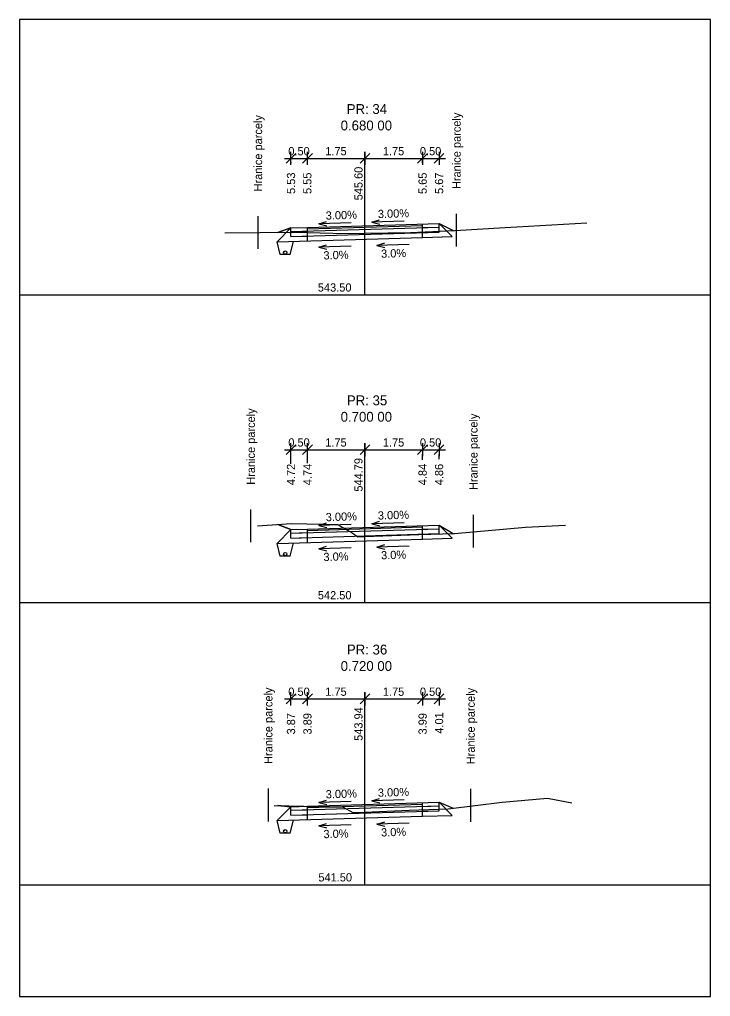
# Model space of a CAD drawing. Extents: x -603737 to -603383, y -1112154 to -1112124.
# Drawn here: x -603429.24 to -603408.24, y -1112153.84 to -1112124.14 of the extents above; entities that cross this region are included whole.
import ezdxf

# ---------------------------------------------------------------- set-up
doc = ezdxf.new("R2010")
doc.units = 0
for name, color, linetype in [('_křivky z hran', 7, 'Continuous'), ('_netisk', 7, 'Continuous'), ('C3D_Podsestava-Popis', 7, 'Continuous'), ('C3D_PP-Popisek', 7, 'Continuous'), ('C3D_PR', 7, 'Continuous'), ('C3D_ZPR', 7, 'Continuous'), ('Default', 7, 'Continuous'), ('konstrukce', 7, 'Continuous')]:
    doc.layers.add(name, color=color, linetype=linetype)

# ---------------------------------------------------------------- blocks, each defined once
blk = doc.blocks.new('_Oblique')
at = {"layer": 'Default'}
blk.add_line((-0.5, -0.5), (0.5, 0.5), dxfattribs=at)
blk = doc.blocks.new('AeccTickLine')
at = {"layer": 'Default'}
blk.add_line((0, 1), (0, -1), dxfattribs=at)

msp = doc.modelspace()

# ---------------------------------------------------------------- linework, layer by layer
at = {"layer": '_netisk'}
msp.add_lwpolyline([(-603429.236, -1112153.84), (-603408.236, -1112153.84), (-603408.236, -1112124.14), (-603429.236, -1112124.14)], close=True, dxfattribs=at)
at = {"layer": 'C3D_Podsestava-Popis'}
for p, q in [((-603421.186, -1112128.361), (-603418.736, -1112128.361)), ((-603418.736, -1112128.361), (-603416.286, -1112128.361)), ((-603416.986, -1112128.511), (-603416.986, -1112128.357)), ((-603416.486, -1112128.342), (-603416.486, -1112128.511)), ((-603420.986, -1112128.477), (-603420.986, -1112128.511)), ((-603420.486, -1112128.511), (-603420.486, -1112128.462)), ((-603418.736, -1112128.511), (-603418.736, -1112128.409)), ((-603421.186, -1112137.217), (-603418.736, -1112137.217)), ((-603418.736, -1112137.217), (-603416.286, -1112137.217)), ((-603420.986, -1112137.645), (-603420.986, -1112137.367)), ((-603420.486, -1112137.63), (-603420.486, -1112137.367)), ((-603418.736, -1112137.577), (-603418.736, -1112137.367)), ((-603416.986, -1112137.525), (-603416.986, -1112137.367)), ((-603416.486, -1112137.51), (-603416.486, -1112137.367)), ((-603421.186, -1112144.794), (-603418.736, -1112144.794)), ((-603418.736, -1112144.794), (-603416.286, -1112144.794)), ((-603418.736, -1112146.003), (-603418.736, -1112144.944))]:
    msp.add_line(p, q, dxfattribs=at)
at = {"layer": 'C3D_PP-Popisek'}
for p, q in [((-603420.139, -1112130.351), (-603419.902, -1112130.276)), ((-603419.155, -1112130.322), (-603420.139, -1112130.351)), ((-603420.139, -1112130.351), (-603419.898, -1112130.412)), ((-603418.528, -1112130.303), (-603418.291, -1112130.227)), ((-603417.544, -1112130.273), (-603418.528, -1112130.303)), ((-603418.528, -1112130.303), (-603418.287, -1112130.364)), ((-603420.139, -1112131.061), (-603419.902, -1112130.986)), ((-603419.155, -1112131.032), (-603420.139, -1112131.061)), ((-603418.374, -1112131.008), (-603418.138, -1112130.933)), ((-603417.391, -1112130.979), (-603418.374, -1112131.008)), ((-603418.374, -1112131.008), (-603418.134, -1112131.069)), ((-603420.139, -1112131.061), (-603419.898, -1112131.122)), ((-603420.139, -1112139.519), (-603419.902, -1112139.444)), ((-603419.155, -1112139.49), (-603420.139, -1112139.519)), ((-603420.139, -1112139.519), (-603419.898, -1112139.58)), ((-603418.528, -1112139.471), (-603418.291, -1112139.395)), ((-603417.544, -1112139.441), (-603418.528, -1112139.471)), ((-603418.528, -1112139.471), (-603418.287, -1112139.532)), ((-603420.139, -1112140.229), (-603419.902, -1112140.154)), ((-603419.155, -1112140.2), (-603420.139, -1112140.229)), ((-603420.139, -1112140.229), (-603419.898, -1112140.29)), ((-603418.374, -1112140.176), (-603418.138, -1112140.101)), ((-603417.391, -1112140.147), (-603418.374, -1112140.176)), ((-603418.374, -1112140.176), (-603418.134, -1112140.237)), ((-603420.139, -1112147.945), (-603419.902, -1112147.87)), ((-603419.155, -1112147.916), (-603420.139, -1112147.945)), ((-603420.139, -1112147.945), (-603419.898, -1112148.006)), ((-603418.528, -1112147.897), (-603418.291, -1112147.821)), ((-603417.544, -1112147.867), (-603418.528, -1112147.897)), ((-603418.528, -1112147.897), (-603418.287, -1112147.958)), ((-603418.374, -1112148.603), (-603418.138, -1112148.527)), ((-603417.391, -1112148.573), (-603418.374, -1112148.603)), ((-603420.139, -1112148.656), (-603419.902, -1112148.58)), ((-603419.155, -1112148.626), (-603420.139, -1112148.656)), ((-603420.139, -1112148.656), (-603419.898, -1112148.717)), ((-603418.374, -1112148.603), (-603418.134, -1112148.664))]:
    msp.add_line(p, q, dxfattribs=at)
at = {"layer": 'C3D_PR'}
for points in [[(-603422.997, -1112130.625), (-603420.874, -1112130.607), (-603419.314, -1112130.648), (-603418.736, -1112130.638), (-603417.356, -1112130.613), (-603416.001, -1112130.553), (-603414.48, -1112130.462), (-603411.991, -1112130.32)], [(-603422.003, -1112139.528), (-603420.968, -1112139.46), (-603419.571, -1112139.493), (-603419.129, -1112139.748), (-603418.951, -1112139.862), (-603418.736, -1112139.855), (-603417.104, -1112139.8), (-603416.015, -1112139.761), (-603413.853, -1112139.573), (-603412.644, -1112139.511)], [(-603421.497, -1112148.031), (-603420.592, -1112148.052), (-603419.396, -1112148.085), (-603419.106, -1112148.252), (-603418.736, -1112148.235), (-603417.397, -1112148.174), (-603416.213, -1112148.134), (-603414.566, -1112147.93), (-603413.19, -1112147.813), (-603412.453, -1112147.95)]]:
    msp.add_lwpolyline(points, dxfattribs=at)
at = {"layer": 'C3D_ZPR'}
for p, q in [((-603418.736, -1112132.511), (-603418.736, -1112128.511)), ((-603421.987, -1112131.116), (-603421.987, -1112130.116)), ((-603415.952, -1112131.043), (-603415.952, -1112130.043)), ((-603420.986, -1112130.587), (-603416.486, -1112130.452)), ((-603420.486, -1112130.462), (-603416.486, -1112130.342)), ((-603420.486, -1112130.502), (-603416.986, -1112130.397)), ((-603416.986, -1112130.397), (-603416.986, -1112130.357)), ((-603416.986, -1112130.767), (-603416.986, -1112130.357)), ((-603416.986, -1112130.467), (-603416.486, -1112130.452)), ((-603416.486, -1112130.602), (-603416.486, -1112130.342)), ((-603416.486, -1112130.602), (-603416.486, -1112130.342)), ((-603416.486, -1112130.342), (-603416.088, -1112130.74)), ((-603416.486, -1112130.342), (-603416.061, -1112130.555)), ((-603416.486, -1112130.342), (-603416.061, -1112130.555)), ((-603421.409, -1112130.899), (-603420.986, -1112130.477)), ((-603420.986, -1112130.477), (-603421.381, -1112130.611)), ((-603421.381, -1112130.611), (-603420.986, -1112130.477)), ((-603420.986, -1112130.477), (-603420.486, -1112130.462)), ((-603420.986, -1112130.737), (-603420.986, -1112130.477)), ((-603420.986, -1112130.737), (-603420.986, -1112130.477)), ((-603420.986, -1112130.587), (-603420.486, -1112130.572)), ((-603420.986, -1112130.737), (-603416.486, -1112130.602)), ((-603420.986, -1112130.737), (-603420.486, -1112130.722)), ((-603420.486, -1112130.872), (-603420.486, -1112130.462)), ((-603420.486, -1112130.572), (-603420.486, -1112130.502)), ((-603420.486, -1112130.872), (-603420.486, -1112130.722)), ((-603416.986, -1112130.617), (-603416.986, -1112130.467)), ((-603416.986, -1112130.617), (-603416.486, -1112130.602)), ((-603416.986, -1112130.767), (-603416.088, -1112130.74)), ((-603421.409, -1112130.899), (-603416.986, -1112130.767)), ((-603429.236, -1112132.511), (-603408.236, -1112132.511)), ((-603418.736, -1112141.867), (-603418.736, -1112137.367)), ((-603422.205, -1112140.033), (-603422.205, -1112139.033)), ((-603415.44, -1112140.193), (-603415.44, -1112139.193)), ((-603421.409, -1112140.067), (-603420.986, -1112139.645)), ((-603420.986, -1112139.645), (-603421.381, -1112139.487)), ((-603421.381, -1112139.487), (-603420.986, -1112139.645)), ((-603420.986, -1112139.755), (-603416.486, -1112139.62)), ((-603420.986, -1112139.645), (-603420.486, -1112139.63)), ((-603420.986, -1112139.905), (-603420.986, -1112139.645)), ((-603420.986, -1112139.905), (-603420.986, -1112139.645)), ((-603420.486, -1112139.63), (-603416.486, -1112139.51)), ((-603420.486, -1112139.67), (-603416.986, -1112139.565)), ((-603420.486, -1112140.04), (-603420.486, -1112139.63)), ((-603416.986, -1112139.565), (-603416.986, -1112139.525)), ((-603416.986, -1112139.935), (-603416.986, -1112139.525)), ((-603416.986, -1112139.635), (-603416.486, -1112139.62)), ((-603416.986, -1112139.785), (-603416.986, -1112139.635)), ((-603416.486, -1112139.77), (-603416.486, -1112139.51)), ((-603416.486, -1112139.77), (-603416.486, -1112139.51)), ((-603416.486, -1112139.51), (-603416.088, -1112139.908)), ((-603416.486, -1112139.51), (-603416.061, -1112139.762)), ((-603416.486, -1112139.51), (-603416.061, -1112139.762)), ((-603421.409, -1112140.067), (-603416.986, -1112139.935)), ((-603420.986, -1112139.755), (-603420.486, -1112139.74)), ((-603420.986, -1112139.905), (-603416.486, -1112139.77)), ((-603420.986, -1112139.905), (-603420.486, -1112139.89)), ((-603420.486, -1112139.74), (-603420.486, -1112139.67)), ((-603420.486, -1112140.04), (-603420.486, -1112139.89)), ((-603416.986, -1112139.785), (-603416.486, -1112139.77)), ((-603416.986, -1112139.935), (-603416.088, -1112139.908)), ((-603429.236, -1112141.867), (-603408.236, -1112141.867)), ((-603418.736, -1112150.444), (-603418.736, -1112144.944)), ((-603421.674, -1112148.521), (-603421.674, -1112147.521)), ((-603415.524, -1112148.532), (-603415.524, -1112147.532)), ((-603420.486, -1112148.056), (-603416.486, -1112147.936)), ((-603416.986, -1112147.991), (-603416.986, -1112147.951)), ((-603416.986, -1112148.361), (-603416.986, -1112147.951)), ((-603416.486, -1112148.196), (-603416.486, -1112147.936)), ((-603416.486, -1112148.196), (-603416.486, -1112147.936)), ((-603416.486, -1112147.936), (-603416.088, -1112148.334)), ((-603416.486, -1112147.936), (-603416.061, -1112148.115)), ((-603416.486, -1112147.936), (-603416.061, -1112148.115)), ((-603421.409, -1112148.494), (-603420.986, -1112148.071)), ((-603420.986, -1112148.071), (-603421.381, -1112148.034)), ((-603421.381, -1112148.034), (-603420.986, -1112148.071)), ((-603420.986, -1112148.181), (-603416.486, -1112148.046)), ((-603420.986, -1112148.071), (-603420.486, -1112148.056)), ((-603420.986, -1112148.331), (-603420.986, -1112148.071)), ((-603420.986, -1112148.331), (-603420.986, -1112148.071)), ((-603420.986, -1112148.181), (-603420.486, -1112148.166)), ((-603420.986, -1112148.331), (-603416.486, -1112148.196)), ((-603420.486, -1112148.096), (-603416.986, -1112147.991)), ((-603420.486, -1112148.466), (-603420.486, -1112148.056)), ((-603420.486, -1112148.166), (-603420.486, -1112148.096)), ((-603416.986, -1112148.061), (-603416.486, -1112148.046)), ((-603416.986, -1112148.211), (-603416.986, -1112148.061)), ((-603416.986, -1112148.211), (-603416.486, -1112148.196)), ((-603421.409, -1112148.494), (-603416.986, -1112148.361)), ((-603420.986, -1112148.331), (-603420.486, -1112148.316)), ((-603420.486, -1112148.466), (-603420.486, -1112148.316)), ((-603416.986, -1112148.361), (-603416.088, -1112148.334)), ((-603429.236, -1112150.444), (-603408.236, -1112150.444))]:
    msp.add_line(p, q, dxfattribs=at)
at = {"layer": 'konstrukce'}
for p, q in [((-603421.312, -1112131.284), (-603421.409, -1112130.899)), ((-603421.012, -1112131.284), (-603420.912, -1112130.884)), ((-603421.012, -1112131.284), (-603421.312, -1112131.284)), ((-603421.312, -1112140.452), (-603421.409, -1112140.067)), ((-603421.012, -1112140.452), (-603420.912, -1112140.052)), ((-603421.012, -1112140.452), (-603421.312, -1112140.452)), ((-603421.312, -1112148.879), (-603421.409, -1112148.494)), ((-603421.012, -1112148.879), (-603420.912, -1112148.479)), ((-603421.012, -1112148.879), (-603421.312, -1112148.879))]:
    msp.add_line(p, q, dxfattribs=at)
for centre in [(-603421.162, -1112131.224), (-603421.162, -1112140.392), (-603421.162, -1112148.819)]:
    msp.add_circle(centre, 0.05, dxfattribs=at)

# ---------------------------------------------------------------- block references
at = {"layer": '_křivky z hran', "rotation": 180}
for name, p, xscale, yscale in [('_Oblique', (-603420.986, -1112128.361), 0.3, 0.3), ('AeccTickLine', (-603420.986, -1112128.361), 0.2, 0.20000000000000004), ('_Oblique', (-603420.486, -1112128.361), 0.3, 0.3), ('AeccTickLine', (-603420.486, -1112128.361), 0.2, 0.20000000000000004), ('_Oblique', (-603418.736, -1112128.361), 0.3, 0.3), ('AeccTickLine', (-603418.736, -1112128.361), 0.2, 0.20000000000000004), ('_Oblique', (-603420.986, -1112137.217), 0.3, 0.3), ('AeccTickLine', (-603420.986, -1112137.217), 0.2, 0.20000000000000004), ('_Oblique', (-603420.486, -1112137.217), 0.3, 0.3), ('AeccTickLine', (-603420.486, -1112137.217), 0.2, 0.20000000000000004), ('_Oblique', (-603418.736, -1112137.217), 0.3, 0.3), ('AeccTickLine', (-603418.736, -1112137.217), 0.2, 0.20000000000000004), ('_Oblique', (-603420.986, -1112144.794), 0.3, 0.3), ('AeccTickLine', (-603420.986, -1112144.794), 0.2, 0.20000000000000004), ('_Oblique', (-603420.486, -1112144.794), 0.3, 0.3), ('AeccTickLine', (-603420.486, -1112144.794), 0.2, 0.20000000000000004), ('_Oblique', (-603418.736, -1112144.794), 0.3, 0.3), ('AeccTickLine', (-603418.736, -1112144.794), 0.2, 0.20000000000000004)]:
    msp.add_blockref(name, p, dxfattribs=dict(at, xscale=xscale, yscale=yscale))
at = {"layer": '_křivky z hran'}
for name, p, xscale, yscale in [('_Oblique', (-603418.736, -1112128.361), 0.3, 0.3), ('AeccTickLine', (-603418.736, -1112128.361), 0.2, 0.20000000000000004), ('_Oblique', (-603416.986, -1112128.361), 0.3, 0.3), ('AeccTickLine', (-603416.986, -1112128.361), 0.2, 0.20000000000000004), ('_Oblique', (-603416.486, -1112128.361), 0.3, 0.3), ('AeccTickLine', (-603416.486, -1112128.361), 0.2, 0.20000000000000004), ('_Oblique', (-603418.736, -1112137.217), 0.3, 0.3), ('AeccTickLine', (-603418.736, -1112137.217), 0.2, 0.20000000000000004), ('_Oblique', (-603416.986, -1112137.217), 0.3, 0.3), ('AeccTickLine', (-603416.986, -1112137.217), 0.2, 0.20000000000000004), ('_Oblique', (-603416.486, -1112137.217), 0.3, 0.3), ('AeccTickLine', (-603416.486, -1112137.217), 0.2, 0.20000000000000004), ('_Oblique', (-603418.736, -1112144.794), 0.3, 0.3), ('AeccTickLine', (-603418.736, -1112144.794), 0.2, 0.20000000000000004), ('_Oblique', (-603416.986, -1112144.794), 0.3, 0.3), ('AeccTickLine', (-603416.986, -1112144.794), 0.2, 0.20000000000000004), ('_Oblique', (-603416.486, -1112144.794), 0.3, 0.3), ('AeccTickLine', (-603416.486, -1112144.794), 0.2, 0.20000000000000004)]:
    msp.add_blockref(name, p, dxfattribs=dict(at, xscale=xscale, yscale=yscale))

# ---------------------------------------------------------------- texts
at = {"layer": 'C3D_Podsestava-Popis'}
for s, rotation, p in [('0.50', 360, (-603421.067, -1112128.267)), ('1.75', 360, (-603419.944, -1112128.267)), ('1.75', 360, (-603419.944, -1112128.267)), ('1.75', 360, (-603418.194, -1112128.267)), ('1.75', 360, (-603418.194, -1112128.267)), ('0.50', 360, (-603417.067, -1112128.267)), ('545.60', 90, (-603418.81, -1112129.637)), ('5.53', 90, (-603420.86, -1112129.443)), ('5.53', 90, (-603420.86, -1112129.443)), ('5.55', 90, (-603420.364, -1112129.444)), ('5.65', 90, (-603416.86, -1112129.444)), ('5.67', 90, (-603416.36, -1112129.443)), ('5.67', 90, (-603416.36, -1112129.443)), ('3.00%', 1.7184, (-603419.926, -1112130.225)), ('3.00%', 1.7184, (-603418.341, -1112130.177)), ('3.0%', 1.7184, (-603419.994, -1112131.436)), ('3.0%', 1.7184, (-603418.244, -1112131.384)), ('0.50', 360, (-603421.067, -1112137.123)), ('1.75', 360, (-603419.944, -1112137.123)), ('1.75', 360, (-603419.944, -1112137.123)), ('1.75', 360, (-603418.194, -1112137.123)), ('1.75', 360, (-603418.194, -1112137.123)), ('0.50', 360, (-603417.067, -1112137.123)), ('544.79', 90, (-603418.81, -1112138.493)), ('4.72', 90, (-603420.86, -1112138.297)), ('4.72', 90, (-603420.86, -1112138.297)), ('4.74', 90, (-603420.361, -1112138.298)), ('4.84', 90, (-603416.86, -1112138.298)), ('4.86', 90, (-603416.36, -1112138.299)), ('4.86', 90, (-603416.36, -1112138.299)), ('3.00%', 1.7184, (-603418.341, -1112139.344)), ('3.00%', 1.7184, (-603419.926, -1112139.393)), ('3.0%', 1.7184, (-603419.994, -1112140.604)), ('3.0%', 1.7184, (-603418.244, -1112140.552)), ('0.50', 360, (-603421.067, -1112144.7)), ('1.75', 360, (-603419.944, -1112144.7)), ('1.75', 360, (-603419.944, -1112144.7)), ('1.75', 360, (-603418.194, -1112144.7)), ('1.75', 360, (-603418.194, -1112144.7)), ('0.50', 360, (-603417.067, -1112144.7)), ('3.87', 90, (-603420.86, -1112145.875)), ('3.87', 90, (-603420.86, -1112145.875)), ('3.89', 90, (-603420.36, -1112145.876)), ('543.94', 90, (-603418.81, -1112146.069)), ('3.99', 90, (-603416.86, -1112145.876)), ('4.01', 90, (-603416.36, -1112145.851)), ('4.01', 90, (-603416.36, -1112145.851)), ('3.00%', 1.7184, (-603419.926, -1112147.819)), ('3.00%', 1.7184, (-603418.341, -1112147.771)), ('3.0%', 1.7184, (-603419.994, -1112149.03)), ('3.0%', 1.7184, (-603418.244, -1112148.978))]:
    msp.add_text(s, height=0.25, rotation=rotation, dxfattribs=at).set_placement(p)
at = {"layer": 'C3D_ZPR'}
for s, p in [('PR: 34', (-603419.291, -1112127.011)), ('0.680 00', (-603419.476, -1112127.511)), ('PR: 35', (-603419.286, -1112135.867)), ('0.700 00', (-603419.476, -1112136.367)), ('PR: 36', (-603419.286, -1112143.444)), ('0.720 00', (-603419.476, -1112143.944))]:
    msp.add_text(s, height=0.3, dxfattribs=at).set_placement(p)
for s, rotation, p in [('Hranice parcely', 90, (-603421.862, -1112129.366)), ('Hranice parcely', 90, (-603415.827, -1112129.293)), ('543.50', 360, (-603420.169, -1112132.411)), ('Hranice parcely', 90, (-603422.08, -1112138.283)), ('Hranice parcely', 90, (-603415.315, -1112138.443)), ('542.50', 360, (-603420.169, -1112141.767)), ('Hranice parcely', 90, (-603421.549, -1112146.771)), ('Hranice parcely', 90, (-603415.399, -1112146.782)), ('541.50', 360, (-603420.153, -1112150.344))]:
    msp.add_text(s, height=0.25, rotation=rotation, dxfattribs=at).set_placement(p)

doc.saveas('drawing.dxf')
